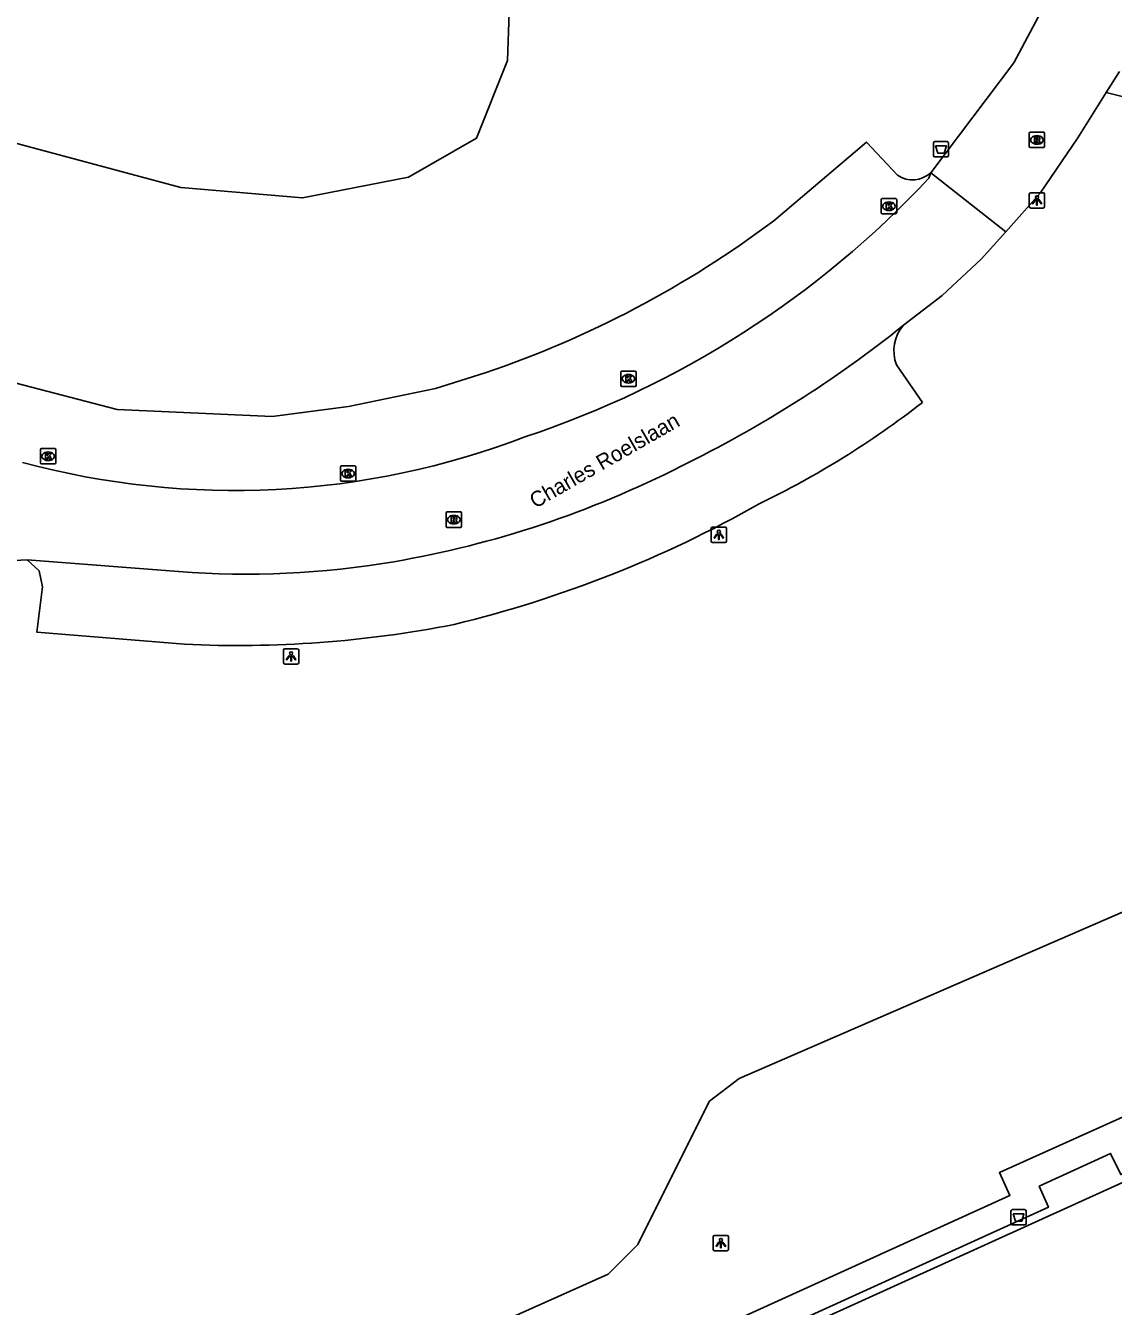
# Model space of a CAD drawing. Extents: x 161094 to 161705, y 379509 to 380907.
# Drawn here: x 161218.5 to 161289.1, y 380040.8 to 380124 of the extents above; entities that cross this region are included whole.
import ezdxf

# ---------------------------------------------------------------- set-up
doc = ezdxf.new("R2010")
doc.units = 0
for name, color, linetype in [('IMGEO_Afvalbak', 7, 'Continuous'), ('IMGEO_Hek', 7, 'Continuous'), ('IMGEO_Kolk', 7, 'Continuous'), ('IMGEO_Lichtpunt', 7, 'Continuous'), ('IMGEO_Loofbos', 7, 'Continuous'), ('IMGEO_Openbare_ruimte_label', 7, 'Continuous'), ('IMGEO_Parkeervlak_gesloten', 7, 'Continuous'), ('IMGEO_Rijbaan_lokaal_gesloten', 7, 'Continuous'), ('IMGEO_Rioolput', 7, 'Continuous'), ('IMGEO_Voetpad_open', 7, 'Continuous'), ('IMGEO_Waterloop', 7, 'Continuous')]:
    doc.layers.add(name, color=color, linetype=linetype)

msp = doc.modelspace()

# ---------------------------------------------------------------- linework, layer by layer
at = {"layer": 'IMGEO_Afvalbak'}
for p, q in [((161277.425, 380115.546), (161277.425, 380116.346)), ((161277.425, 380116.346), (161277.425, 380115.546)), ((161277.525, 380116.446), (161278.315, 380116.446)), ((161278.315, 380116.446), (161277.525, 380116.446)), ((161278.415, 380116.346), (161278.415, 380115.546)), ((161278.415, 380115.546), (161278.415, 380116.346)), ((161278.315, 380115.446), (161277.525, 380115.446)), ((161277.525, 380115.446), (161278.315, 380115.446)), ((161282.463, 380046.177), (161282.463, 380046.977)), ((161282.463, 380046.977), (161282.463, 380046.177)), ((161282.563, 380047.077), (161283.353, 380047.077)), ((161283.353, 380047.077), (161282.563, 380047.077)), ((161283.453, 380046.977), (161283.453, 380046.177)), ((161283.453, 380046.177), (161283.453, 380046.977)), ((161283.353, 380046.077), (161282.563, 380046.077)), ((161282.563, 380046.077), (161283.353, 380046.077))]:
    msp.add_line(p, q, dxfattribs=at)
for points in [[(161277.568, 380116.16), (161278.272, 380116.16), (161278.123, 380115.69), (161277.717, 380115.69), (161277.568, 380116.16)], [(161282.606, 380046.791), (161283.31, 380046.791), (161283.161, 380046.321), (161282.755, 380046.321), (161282.606, 380046.791)]]:
    msp.add_lwpolyline(points, dxfattribs=at)
for centre, start, end in [((161277.525, 380116.346), 90, 180), ((161277.525, 380116.346), 90, 180), ((161278.315, 380116.346), 0, 90), ((161278.315, 380116.346), 360, 90), ((161277.525, 380115.546), 180, 270), ((161277.525, 380115.546), 180, 270), ((161278.315, 380115.546), 270, 0), ((161278.315, 380115.546), 270, 0), ((161282.563, 380046.977), 90, 180), ((161282.563, 380046.977), 90, 180), ((161283.353, 380046.977), 0, 90), ((161283.353, 380046.977), 360, 90), ((161282.563, 380046.177), 180, 270), ((161282.563, 380046.177), 180, 270), ((161283.353, 380046.177), 270, 0), ((161283.353, 380046.177), 270, 0)]:
    msp.add_arc(centre, 0.1, start, end, dxfattribs=at)
at = {"layer": 'IMGEO_Hek'}
msp.add_lwpolyline([(161282.49, 379981.114), (161272.326, 379976.507), (161272.946, 379975.155), (161268.403, 379973.073), (161267.745, 379974.424), (161245.458, 379964.327), (161243.588, 379968.636), (161221.01, 380018.226), (161243.313, 380028.348), (161242.697, 380029.7), (161247.399, 380031.857), (161248.045, 380030.463), (161284.892, 380047.225), (161284.302, 380048.589), (161288.939, 380050.72), (161289.598, 380049.351), (161311.663, 380059.359), (161336.159, 380005.46), (161313.894, 379995.295), (161314.507, 379993.981), (161309.839, 379991.856), (161309.202, 379993.224), (161299.077, 379988.609)], dxfattribs=at)
at = {"layer": 'IMGEO_Kolk'}
for p, q in [((161274.042, 380111.822), (161274.042, 380112.674)), ((161274.117, 380112.748), (161274.969, 380112.748)), ((161274.53, 380112.528), (161274.555, 380112.528)), ((161275.043, 380112.674), (161275.043, 380111.822)), ((161274.969, 380111.748), (161274.117, 380111.748)), ((161274.553, 380111.968), (161274.528, 380111.968)), ((161257.126, 380100.616), (161257.126, 380101.468)), ((161257.201, 380101.542), (161258.053, 380101.542)), ((161257.614, 380101.322), (161257.639, 380101.322)), ((161258.127, 380101.468), (161258.127, 380100.616)), ((161258.053, 380100.542), (161257.201, 380100.542)), ((161257.637, 380100.762), (161257.612, 380100.762)), ((161219.439, 380095.581), (161219.439, 380096.433)), ((161219.514, 380096.507), (161220.366, 380096.507)), ((161219.927, 380096.287), (161219.952, 380096.287)), ((161220.44, 380096.433), (161220.44, 380095.581)), ((161220.366, 380095.507), (161219.514, 380095.507)), ((161219.95, 380095.727), (161219.925, 380095.727)), ((161238.918, 380094.458), (161238.918, 380095.31)), ((161238.993, 380095.384), (161239.845, 380095.384)), ((161239.406, 380095.164), (161239.431, 380095.164)), ((161239.919, 380095.31), (161239.919, 380094.458)), ((161239.845, 380094.384), (161238.993, 380094.384)), ((161239.429, 380094.604), (161239.404, 380094.604))]:
    msp.add_line(p, q, dxfattribs=at)
for points in [[(161274.042, 380111.822), (161274.042, 380112.674)], [(161274.117, 380112.748), (161274.969, 380112.748)], [(161275.043, 380112.674), (161275.043, 380111.822)], [(161274.969, 380111.748), (161274.117, 380111.748)], [(161274.363, 380112.448), (161274.486, 380112.448), (161274.486, 380112.297), (161274.616, 380112.448), (161274.78, 380112.448), (161274.634, 380112.297), (161274.787, 380112.048), (161274.635, 380112.048), (161274.55, 380112.212), (161274.486, 380112.145), (161274.486, 380112.048), (161274.363, 380112.048), (161274.363, 380112.448)], [(161257.126, 380100.616), (161257.126, 380101.468)], [(161257.201, 380101.542), (161258.053, 380101.542)], [(161257.447, 380101.242), (161257.57, 380101.242), (161257.57, 380101.091), (161257.7, 380101.242), (161257.864, 380101.242), (161257.718, 380101.091), (161257.871, 380100.842), (161257.719, 380100.842), (161257.634, 380101.006), (161257.57, 380100.939), (161257.57, 380100.842), (161257.447, 380100.842), (161257.447, 380101.242)], [(161258.127, 380101.468), (161258.127, 380100.616)], [(161258.053, 380100.542), (161257.201, 380100.542)], [(161219.439, 380095.581), (161219.439, 380096.433)], [(161219.514, 380096.507), (161220.366, 380096.507)], [(161219.76, 380096.207), (161219.883, 380096.207), (161219.883, 380096.056), (161220.013, 380096.207), (161220.177, 380096.207), (161220.031, 380096.056), (161220.184, 380095.807), (161220.032, 380095.807), (161219.947, 380095.971), (161219.883, 380095.904), (161219.883, 380095.807), (161219.76, 380095.807), (161219.76, 380096.207)], [(161220.44, 380096.433), (161220.44, 380095.581)], [(161220.366, 380095.507), (161219.514, 380095.507)], [(161238.918, 380094.458), (161238.918, 380095.31)], [(161238.993, 380095.384), (161239.845, 380095.384)], [(161239.239, 380095.084), (161239.362, 380095.084), (161239.362, 380094.933), (161239.492, 380095.084), (161239.656, 380095.084), (161239.51, 380094.933), (161239.663, 380094.684), (161239.511, 380094.684), (161239.426, 380094.848), (161239.362, 380094.781), (161239.362, 380094.684), (161239.239, 380094.684), (161239.239, 380095.084)], [(161239.919, 380095.31), (161239.919, 380094.458)], [(161239.845, 380094.384), (161238.993, 380094.384)]]:
    msp.add_lwpolyline(points, dxfattribs=at)
for centre, start, end in [((161274.119, 380112.672), 91.55205, 178.44795), ((161274.119, 380112.672), 91.55205, 178.44795), ((161274.967, 380112.672), 1.55205, 88.44795), ((161274.967, 380112.672), 1.55205, 88.44795), ((161274.119, 380111.824), 181.55205, 268.44795), ((161274.119, 380111.824), 181.55205, 268.44795), ((161274.967, 380111.824), 271.55205, 358.44795), ((161274.967, 380111.824), 271.55205, 358.44795), ((161257.203, 380101.466), 91.55205, 178.44795), ((161257.203, 380101.466), 91.55205, 178.44795), ((161258.051, 380101.466), 1.55205, 88.44795), ((161258.051, 380101.466), 1.55205, 88.44795), ((161257.203, 380100.618), 181.55205, 268.44795), ((161257.203, 380100.618), 181.55205, 268.44795), ((161258.051, 380100.618), 271.55205, 358.44795), ((161258.051, 380100.618), 271.55205, 358.44795), ((161219.516, 380096.431), 91.55205, 178.44795), ((161219.516, 380096.431), 91.55205, 178.44795), ((161220.364, 380096.431), 1.55205, 88.44795), ((161220.364, 380096.431), 1.55205, 88.44795), ((161219.516, 380095.583), 181.55205, 268.44795), ((161219.516, 380095.583), 181.55205, 268.44795), ((161220.364, 380095.583), 271.55205, 358.44795), ((161220.364, 380095.583), 271.55205, 358.44795), ((161238.995, 380095.308), 91.55205, 178.44795), ((161238.995, 380095.308), 91.55205, 178.44795), ((161239.843, 380095.308), 1.55205, 88.44795), ((161239.843, 380095.308), 1.55205, 88.44795), ((161238.995, 380094.46), 181.55205, 268.44795), ((161238.995, 380094.46), 181.55205, 268.44795), ((161239.843, 380094.46), 271.55205, 358.44795), ((161239.843, 380094.46), 271.55205, 358.44795)]:
    msp.add_arc(centre, 0.0765, start, end, dxfattribs=at)
for centre, major_axis, ratio, start_param, end_param in [((161274.529, 380112.248), (-0.387, 0.002), 0.722429, 4.712389, 7.853982), ((161274.554, 380112.248), (-0.39, 0.002), 0.717154, 1.570796, 4.712389), ((161257.613, 380101.042), (-0.387, 0.002), 0.722429, 4.712389, 7.853982), ((161257.638, 380101.042), (-0.39, 0.002), 0.717154, 1.570796, 4.712389), ((161219.926, 380096.007), (-0.387, 0.002), 0.722429, 4.712389, 7.853982), ((161219.951, 380096.007), (-0.39, 0.002), 0.717154, 1.570796, 4.712389), ((161239.405, 380094.884), (-0.387, 0.002), 0.722429, 4.712389, 7.853982), ((161239.43, 380094.884), (-0.39, 0.002), 0.717154, 1.570796, 4.712389)]:
    msp.add_ellipse(centre, major_axis=major_axis, ratio=ratio, start_param=start_param, end_param=end_param, dxfattribs=at)
at = {"layer": 'IMGEO_Lichtpunt'}
for p, q in [((161283.654, 380113.032), (161283.654, 380112.225)), ((161283.654, 380113.032), (161283.654, 380112.225)), ((161284.556, 380113.127), (161283.748, 380113.127)), ((161284.556, 380113.127), (161283.748, 380113.127)), ((161284.65, 380112.225), (161284.65, 380113.032)), ((161284.65, 380112.225), (161284.65, 380113.032)), ((161283.748, 380112.131), (161284.556, 380112.131)), ((161283.748, 380112.131), (161284.556, 380112.131)), ((161262.995, 380091.309), (161262.995, 380090.502)), ((161262.995, 380091.309), (161262.995, 380090.502)), ((161263.897, 380091.404), (161263.089, 380091.404)), ((161263.897, 380091.404), (161263.089, 380091.404)), ((161263.991, 380090.502), (161263.991, 380091.309)), ((161263.991, 380090.502), (161263.991, 380091.309)), ((161263.089, 380090.408), (161263.897, 380090.408)), ((161263.089, 380090.408), (161263.897, 380090.408)), ((161235.221, 380083.411), (161235.221, 380082.604)), ((161235.221, 380083.411), (161235.221, 380082.604)), ((161236.123, 380083.506), (161235.315, 380083.506)), ((161236.123, 380083.506), (161235.315, 380083.506)), ((161236.217, 380082.604), (161236.217, 380083.411)), ((161236.217, 380082.604), (161236.217, 380083.411)), ((161235.315, 380082.51), (161236.123, 380082.51)), ((161235.315, 380082.51), (161236.123, 380082.51)), ((161263.129, 380045.308), (161263.129, 380044.501)), ((161263.129, 380045.308), (161263.129, 380044.501)), ((161264.031, 380045.403), (161263.223, 380045.403)), ((161264.031, 380045.403), (161263.223, 380045.403)), ((161264.125, 380044.501), (161264.125, 380045.308)), ((161264.125, 380044.501), (161264.125, 380045.308)), ((161263.223, 380044.407), (161264.031, 380044.407)), ((161263.223, 380044.407), (161264.031, 380044.407))]:
    msp.add_line(p, q, dxfattribs=at)
for points in [[(161284.028, 380112.696), (161284.067, 380112.668), (161283.879, 380112.406), (161283.841, 380112.433), (161284.028, 380112.696)], [(161284.13, 380112.648), (161284.177, 380112.648), (161284.177, 380112.326), (161284.13, 380112.326), (161284.13, 380112.648)], [(161284.24, 380112.668), (161284.278, 380112.695), (161284.465, 380112.433), (161284.426, 380112.405), (161284.24, 380112.668)], [(161263.369, 380090.973), (161263.408, 380090.945), (161263.22, 380090.683), (161263.182, 380090.71), (161263.369, 380090.973)], [(161263.471, 380090.925), (161263.518, 380090.925), (161263.518, 380090.603), (161263.471, 380090.603), (161263.471, 380090.925)], [(161263.581, 380090.945), (161263.619, 380090.972), (161263.806, 380090.71), (161263.767, 380090.682), (161263.581, 380090.945)], [(161235.595, 380083.075), (161235.634, 380083.047), (161235.446, 380082.785), (161235.408, 380082.812), (161235.595, 380083.075)], [(161235.697, 380083.027), (161235.744, 380083.027), (161235.744, 380082.705), (161235.697, 380082.705), (161235.697, 380083.027)], [(161235.807, 380083.047), (161235.845, 380083.074), (161236.032, 380082.812), (161235.993, 380082.784), (161235.807, 380083.047)], [(161263.503, 380044.972), (161263.542, 380044.944), (161263.354, 380044.682), (161263.316, 380044.709), (161263.503, 380044.972)], [(161263.605, 380044.924), (161263.652, 380044.924), (161263.652, 380044.602), (161263.605, 380044.602), (161263.605, 380044.924)], [(161263.715, 380044.944), (161263.753, 380044.971), (161263.94, 380044.709), (161263.901, 380044.681), (161263.715, 380044.944)]]:
    msp.add_lwpolyline(points, dxfattribs=at)
for centre in [(161284.153, 380112.83), (161263.494, 380091.107), (161235.72, 380083.209), (161263.628, 380045.106)]:
    msp.add_circle(centre, 0.0994, dxfattribs=at)
for centre, start, end in [((161283.748, 380113.032), 90, 180), ((161283.748, 380113.032), 90, 180), ((161284.556, 380113.032), 0, 90), ((161284.556, 380113.032), 0, 90), ((161283.748, 380112.225), 180, 270), ((161283.748, 380112.225), 180, 270), ((161284.556, 380112.225), 270, 0), ((161284.556, 380112.225), 270, 360), ((161263.089, 380091.309), 90, 180), ((161263.089, 380091.309), 90, 180), ((161263.897, 380091.309), 0, 90), ((161263.897, 380091.309), 0, 90), ((161263.089, 380090.502), 180, 270), ((161263.089, 380090.502), 180, 270), ((161263.897, 380090.502), 270, 0), ((161263.897, 380090.502), 270, 360), ((161235.315, 380083.411), 90, 180), ((161235.315, 380083.411), 90, 180), ((161236.123, 380083.411), 0, 90), ((161236.123, 380083.411), 0, 90), ((161235.315, 380082.604), 180, 270), ((161235.315, 380082.604), 180, 270), ((161236.123, 380082.604), 270, 0), ((161236.123, 380082.604), 270, 360), ((161263.223, 380045.308), 90, 180), ((161263.223, 380045.308), 90, 180), ((161264.031, 380045.308), 0, 90), ((161264.031, 380045.308), 0, 90), ((161263.223, 380044.501), 180, 270), ((161263.223, 380044.501), 180, 270), ((161264.031, 380044.501), 270, 0), ((161264.031, 380044.501), 270, 360)]:
    msp.add_arc(centre, 0.0946, start, end, dxfattribs=at)
at = {"layer": 'IMGEO_Loofbos'}
msp.add_lwpolyline([(161244.332, 379950.948), (161212.115, 380023.104), (161256.315, 380042.888), (161257.86, 380044.434), (161258.233, 380044.807), (161259.172, 380046.687), (161262.89, 380054.125), (161264.808, 380055.587), (161305.516, 380073.263), (161306.926, 380074.038)], dxfattribs=at)
at = {"layer": 'IMGEO_Parkeervlak_gesloten'}
for points in [[(161267.061, 380111.307), (161273.075, 380116.41), (161275.095, 380114.256)], [(161277.27, 380114.427), (161277.14, 380114.078)], [(161275.496, 380104.524), (161278.005, 380106.449), (161280.535, 380108.799), (161282.126, 380110.59)], [(161185.279, 380109.252), (161224.417, 380099.047), (161234.496, 380098.584), (161239.445, 380099.25), (161245.106, 380100.414), (161248.326, 380101.431)], [(161275.041, 380101.945), (161276.712, 380099.498)], [(161212.707, 380086.355), (161213.844, 380087.738), (161215.297, 380088.786), (161216.916, 380089.198), (161218.585, 380089.286)], [(161228.79, 380083.796), (161219.203, 380084.584), (161219.566, 380087.532), (161219.355, 380088.565), (161218.585, 380089.286)], [(161218.585, 380089.286), (161228.417, 380088.513)]]:
    msp.add_lwpolyline(points, dxfattribs=at)
for centre, radius, start, end in [((161276.073, 380115.732), 1.771, 236.46737, 312.5234), ((161231.031, 380157.156), 63.101, 288.41006, 316.94684), ((161227.072, 380164.458), 66.514, 288.63484, 306.95633), ((161226.837, 380165.272), 77.834, 296.07535, 308.69442), ((161277.327, 380102.871), 2.467, 137.93564, 202.05347), ((161240.405, 380146.102), 59.077, 295.79028, 307.92081), ((161232.053, 380146.531), 52.751, 254.85396, 291.00215), ((161231.211, 380153.933), 65.735, 279.7952, 296.99543), ((161228.32, 380159.582), 76.637, 283.56895, 299.5433), ((161232.782, 380145.764), 57.417, 265.63958, 279.63658), ((161232.245, 380156.486), 72.772, 267.27842, 281.13555)]:
    msp.add_arc(centre, radius, start, end, dxfattribs=at)
at = {"layer": 'IMGEO_Rijbaan_lokaal_gesloten'}
for points in [[(161288.728, 380134.19), (161285.114, 380126.208), (161282.644, 380121.57), (161277.27, 380114.427)], [(161289.503, 380120.993), (161288.647, 380119.629)], [(161282.126, 380110.59), (161284.361, 380113.106), (161286.801, 380116.69), (161288.647, 380119.629)], [(161277.27, 380114.427), (161282.126, 380110.59)]]:
    msp.add_lwpolyline(points, dxfattribs=at)
at = {"layer": 'IMGEO_Rioolput'}
for p, q in [((161283.651, 380116.127), (161283.651, 380116.979)), ((161283.726, 380117.053), (161284.578, 380117.053)), ((161284.139, 380116.833), (161284.164, 380116.833)), ((161284.652, 380116.979), (161284.652, 380116.127)), ((161284.578, 380116.053), (161283.726, 380116.053)), ((161284.162, 380116.273), (161284.137, 380116.273)), ((161245.785, 380091.464), (161245.785, 380092.316)), ((161245.86, 380092.39), (161246.712, 380092.39)), ((161246.273, 380092.17), (161246.298, 380092.17)), ((161246.786, 380092.316), (161246.786, 380091.464)), ((161246.712, 380091.39), (161245.86, 380091.39)), ((161246.296, 380091.61), (161246.271, 380091.61))]:
    msp.add_line(p, q, dxfattribs=at)
for points in [[(161283.651, 380116.127), (161283.651, 380116.979)], [(161283.726, 380117.053), (161284.578, 380117.053)], [(161284.24, 380116.751), (161283.988, 380116.753), (161283.988, 380116.353)], [(161284.166, 380116.672), (161284.112, 380116.672), (161284.112, 380116.591)], [(161284.652, 380116.979), (161284.652, 380116.127)], [(161284.578, 380116.053), (161283.726, 380116.053)], [(161283.988, 380116.353), (161284.112, 380116.353), (161284.112, 380116.515), (161284.123, 380116.515)], [(161284.112, 380116.591), (161284.164, 380116.591)], [(161284.17, 380116.486), (161284.241, 380116.353), (161284.381, 380116.353), (161284.316, 380116.479)], [(161245.785, 380091.464), (161245.785, 380092.316)], [(161245.86, 380092.39), (161246.712, 380092.39)], [(161246.374, 380092.088), (161246.122, 380092.09), (161246.122, 380091.69)], [(161246.122, 380091.69), (161246.246, 380091.69), (161246.246, 380091.852), (161246.257, 380091.852)], [(161246.3, 380092.009), (161246.246, 380092.009), (161246.246, 380091.928)], [(161246.246, 380091.928), (161246.298, 380091.928)], [(161246.304, 380091.823), (161246.375, 380091.69), (161246.515, 380091.69), (161246.45, 380091.816)], [(161246.786, 380092.316), (161246.786, 380091.464)], [(161246.712, 380091.39), (161245.86, 380091.39)]]:
    msp.add_lwpolyline(points, dxfattribs=at)
for centre, radius, start, end in [((161283.728, 380116.977), 0.0765, 91.55205, 178.44795), ((161283.728, 380116.977), 0.0765, 91.55205, 178.44795), ((161284.172, 380116.576), 0.0964, 77.00612, 93.18647), ((161284.186, 380116.633), 0.0378, 276.66336, 79.67722), ((161284.239, 380116.641), 0.109, 350.36119, 89.41601), ((161284.576, 380116.977), 0.0765, 1.55205, 88.44795), ((161284.576, 380116.977), 0.0765, 1.55205, 88.44795), ((161283.728, 380116.129), 0.0765, 181.55205, 268.44795), ((161283.728, 380116.129), 0.0765, 181.55205, 268.44795), ((161284.122, 380116.462), 0.0533, 26.02933, 88.69889), ((161284.148, 380116.78), 0.19, 274.7715, 282.96867), ((161284.237, 380116.641), 0.112, 277.58423, 350.98172), ((161284.221, 380116.426), 0.108, 29.51342, 73.79051), ((161284.576, 380116.129), 0.0765, 271.55205, 358.44795), ((161284.576, 380116.129), 0.0765, 271.55205, 358.44795), ((161245.862, 380092.314), 0.0765, 91.55205, 178.44795), ((161245.862, 380092.314), 0.0765, 91.55205, 178.44795), ((161246.256, 380091.799), 0.0533, 26.02933, 88.69889), ((161246.282, 380092.117), 0.19, 274.7715, 282.96867), ((161246.306, 380091.913), 0.0964, 77.00612, 93.18647), ((161246.32, 380091.97), 0.0378, 276.66336, 79.67722), ((161246.373, 380091.978), 0.109, 350.36119, 89.41601), ((161246.371, 380091.978), 0.112, 277.58423, 350.98172), ((161246.355, 380091.763), 0.108, 29.51342, 73.79051), ((161246.71, 380092.314), 0.0765, 1.55205, 88.44795), ((161246.71, 380092.314), 0.0765, 1.55205, 88.44795), ((161245.862, 380091.466), 0.0765, 181.55205, 268.44795), ((161245.862, 380091.466), 0.0765, 181.55205, 268.44795), ((161246.71, 380091.466), 0.0765, 271.55205, 358.44795), ((161246.71, 380091.466), 0.0765, 271.55205, 358.44795)]:
    msp.add_arc(centre, radius, start, end, dxfattribs=at)
for centre, major_axis, ratio, start_param, end_param in [((161284.138, 380116.553), (-0.387, 0.002), 0.722429, 4.712389, 7.853982), ((161284.163, 380116.553), (-0.39, 0.002), 0.717154, 1.570796, 4.712389), ((161246.272, 380091.89), (-0.387, 0.002), 0.722429, 4.712389, 7.853982), ((161246.297, 380091.89), (-0.39, 0.002), 0.717154, 1.570796, 4.712389)]:
    msp.add_ellipse(centre, major_axis=major_axis, ratio=ratio, start_param=start_param, end_param=end_param, dxfattribs=at)
at = {"layer": 'IMGEO_Voetpad_open'}
for points in [[(161288.647, 380119.629), (161292.779, 380118.588)], [(161333.873, 380041.758), (161331.115, 380040.61), (161323.136, 380044.073), (161321.932, 380046.691), (161319.78, 380045.718), (161312.531, 380061.643), (161290.619, 380051.699), (161289.948, 380053.183), (161281.717, 380049.48), (161282.396, 380047.991), (161248.967, 380032.793), (161248.318, 380034.301), (161240.363, 380030.654), (161241.037, 380029.206), (161230.069, 380024.187), (161223.462, 380021.221), (161218.695, 380019.077), (161248.207, 379953.948)], [(161311.457, 380058.707), (161231.045, 380022.212), (161221.64, 380017.991), (161243.977, 379968.805), (161245.706, 379964.978), (161335.517, 380005.692), (161311.457, 380058.707)]]:
    msp.add_lwpolyline(points, dxfattribs=at)
at = {"layer": 'IMGEO_Waterloop'}
msp.add_lwpolyline([(161196.905, 380128.098), (161201.052, 380123.512), (161207.098, 380120.68), (161216.431, 380116.702), (161228.567, 380113.465), (161236.467, 380112.791), (161243.343, 380114.139), (161247.767, 380116.659), (161249.77, 380121.723), (161249.986, 380127.961)], dxfattribs=at)

# ---------------------------------------------------------------- texts
at = {"layer": 'IMGEO_Openbare_ruimte_label'}
msp.add_text('Charles Roelslaan', height=1, rotation=29.79462, dxfattribs=at).set_placement((161251.572, 380092.591))

doc.saveas('drawing.dxf')
